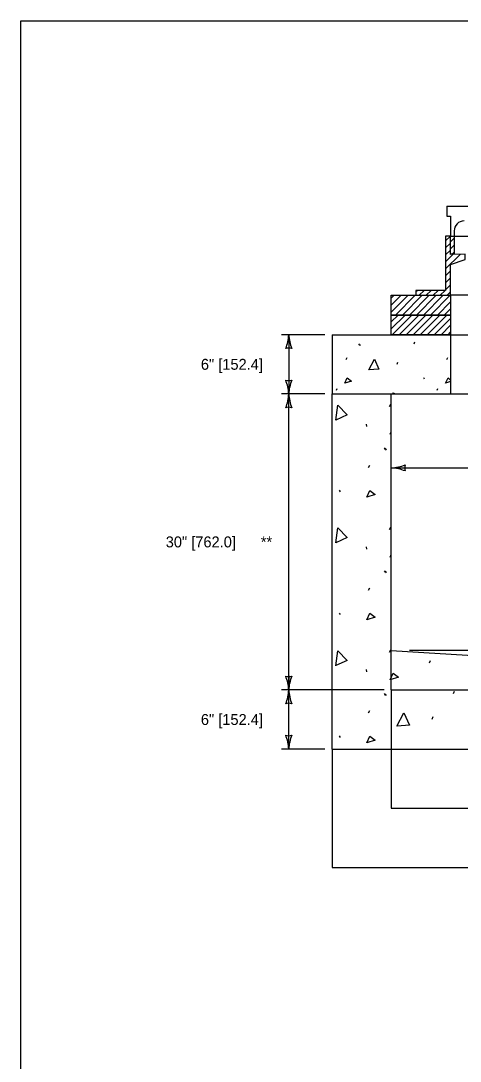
# Model space of a CAD drawing. Extents: x 49991.4 to 50057, y 49987.6 to 50011.4.
# Drawn here: x 49999.38 to 50001.8, y 49993.29 to 49999 of the extents above; entities that cross this region are included whole.
import ezdxf

# ---------------------------------------------------------------- set-up
doc = ezdxf.new("R2010")
doc.units = 0
for name, color, linetype in [('Level 1', 7, 'Continuous'), ('Level 2', 7, 'Continuous'), ('Level 3', 7, 'Continuous'), ('Level 4', 7, 'Continuous')]:
    doc.layers.add(name, color=color, linetype=linetype)

msp = doc.modelspace()

# ---------------------------------------------------------------- linework, layer by layer
at = {"layer": 'Level 1'}
for p, q in [((50001.7226, 49997.9815), (50003.7132, 49997.9815)), ((50001.7226, 49997.9815), (50001.7226, 49997.9273)), ((50001.7226, 49997.9273), (50001.7429, 49997.9273)), ((50001.7429, 49997.9273), (50001.7429, 49997.8173)), ((50001.7632, 49997.846), (50001.7632, 49997.8173)), ((50001.7158, 49997.7903), (50001.7429, 49997.8173)), ((50001.7429, 49997.7853), (50001.7632, 49997.8056)), ((50001.7632, 49997.8173), (50003.6726, 49997.8173)), ((50001.7632, 49997.8173), (50001.7632, 49997.7172)), ((50001.7158, 49997.752), (50001.7429, 49997.7791)), ((50001.7158, 49997.7137), (50001.7429, 49997.7408)), ((50001.7429, 49997.747), (50001.7632, 49997.7673)), ((50001.7515, 49997.7172), (50001.7632, 49997.729)), ((50001.7158, 49997.6371), (50001.7955, 49997.7168)), ((50001.7158, 49997.6754), (50001.7565, 49997.716)), ((50001.7158, 49997.5988), (50001.7429, 49997.6259)), ((50001.7158, 49997.5605), (50001.7429, 49997.5876)), ((50001.5533, 49997.5129), (50001.5599, 49997.5194)), ((50001.5711, 49997.4923), (50001.5982, 49997.5194)), ((50001.6094, 49997.4923), (50001.6365, 49997.5194)), ((50001.6477, 49997.4923), (50001.6748, 49997.5194)), ((50001.686, 49997.4923), (50001.7131, 49997.5194)), ((50001.7158, 49997.5222), (50001.7429, 49997.5493)), ((50001.7243, 49997.4923), (50001.7429, 49997.511)), ((50001.4179, 49997.3994), (50001.5108, 49997.4923)), ((50001.4179, 49997.4377), (50001.4725, 49997.4923)), ((50001.4179, 49997.476), (50001.4342, 49997.4923)), ((50001.4408, 49997.384), (50001.5491, 49997.4923)), ((50001.4791, 49997.384), (50001.5874, 49997.4923)), ((50001.5174, 49997.384), (50001.6257, 49997.4923)), ((50001.5557, 49997.384), (50001.664, 49997.4923)), ((50001.594, 49997.384), (50001.7023, 49997.4923)), ((50001.6323, 49997.384), (50001.7406, 49997.4923)), ((50001.6706, 49997.384), (50001.7429, 49997.4563)), ((50003.6929, 49997.4923), (50001.7429, 49997.4923)), ((50001.7089, 49997.384), (50001.7429, 49997.418)), ((50001.4179, 49997.3088), (50001.4931, 49997.384)), ((50001.4179, 49997.3471), (50001.4548, 49997.384)), ((50001.423, 49997.2757), (50001.5314, 49997.384)), ((50001.4613, 49997.2757), (50001.5697, 49997.384)), ((50001.4996, 49997.2757), (50001.608, 49997.384)), ((50001.5379, 49997.2757), (50001.6463, 49997.384)), ((50001.5762, 49997.2757), (50001.6846, 49997.384)), ((50001.6145, 49997.2757), (50001.7229, 49997.384)), ((50001.6528, 49997.2757), (50001.7429, 49997.3657)), ((50001.6911, 49997.2757), (50001.7429, 49997.3274)), ((50001.0929, 49997.2757), (50001.7429, 49997.2757)), ((50001.0929, 49997.2757), (50001.0929, 49996.9507)), ((50001.7294, 49997.2757), (50001.7429, 49997.2891)), ((50001.7429, 49997.2757), (50001.7429, 49996.9507)), ((50001.7429, 49997.2757), (50003.6929, 49997.2757)), ((50001.2384, 49997.226), (50001.2431, 49997.219)), ((50001.2431, 49997.2233), (50001.2477, 49997.2164)), ((50001.5432, 49997.226), (50001.5478, 49997.2364)), ((50001.1703, 49997.1404), (50001.1749, 49997.1508)), ((50001.4497, 49997.1138), (50001.4543, 49997.1242)), ((50001.7233, 49997.1404), (50001.7279, 49997.1508)), ((50001.594, 49997.04), (50001.5986, 49997.033)), ((50001.7429, 49997.0186), (50001.7152, 49997.0099)), ((50001.0929, 49996.9507), (50001.7429, 49996.9507)), ((50001.0929, 49995.0007), (50001.0929, 49996.9507)), ((50001.0929, 49996.9507), (50004.3429, 49996.9507)), ((50001.1165, 49996.9705), (50001.1211, 49996.9809)), ((50001.4179, 49995.3257), (50001.4179, 49996.9507)), ((50001.6695, 49996.9705), (50001.6741, 49996.9809)), ((50001.4087, 49996.8808), (50001.4145, 49996.8937)), ((50001.2799, 49996.7853), (50001.2814, 49996.7724)), ((50001.4116, 49996.7292), (50001.4179, 49996.7423)), ((50001.4179, 49996.7312), (50001.4116, 49996.7292)), ((50001.3784, 49996.6542), (50001.3842, 49996.6455)), ((50001.3842, 49996.6509), (50001.39, 49996.6422)), ((50001.2933, 49996.5472), (50001.299, 49996.5602)), ((50001.1316, 49996.4217), (50001.1374, 49996.413)), ((50001.4087, 49996.2067), (50001.4145, 49996.2197)), ((50001.2799, 49996.1113), (50001.2814, 49996.0983)), ((50001.4116, 49996.0552), (50001.4179, 49996.0683)), ((50001.4179, 49996.0571), (50001.4116, 49996.0552)), ((50001.3784, 49995.9801), (50001.3842, 49995.9715)), ((50001.3842, 49995.9768), (50001.39, 49995.9682)), ((50001.2933, 49995.8732), (50001.299, 49995.8861)), ((50001.1316, 49995.7476), (50001.1374, 49995.739)), ((50001.4087, 49995.5326), (50001.4145, 49995.5456)), ((50001.4179, 49995.5423), (50004.0179, 49995.3798)), ((50001.6281, 49995.4734), (50001.6338, 49995.4864)), ((50001.2799, 49995.4372), (50001.2814, 49995.4242)), ((50001.3784, 49995.306), (50001.3842, 49995.2974)), ((50001.3842, 49995.3028), (50001.39, 49995.2941)), ((50001.4179, 49995.3257), (50004.0179, 49995.3257)), ((50001.4179, 49995.3257), (50004.0179, 49995.3257)), ((50001.7594, 49995.306), (50001.7652, 49995.319)), ((50001.2933, 49995.1991), (50001.299, 49995.2121)), ((50001.6425, 49995.1659), (50001.6483, 49995.1789)), ((50001.1316, 49995.0735), (50001.1374, 49995.0649)), ((50001.0929, 49995.0007), (50004.3429, 49995.0007)), ((50001.0929, 49995.0007), (50001.0929, 49995.0007))]:
    msp.add_line(p, q, dxfattribs=at)
for points in [[(49999.3835, 49998.9992), (50016.7501, 49998.9992), (50016.7501, 49987.7988), (49999.3835, 49987.7988)], [(50001.7429, 49997.4923), (50001.7429, 49997.6616), (50001.8242, 49997.6887), (50001.8242, 49997.7173), (50001.7429, 49997.7158), (50001.7429, 49997.8173), (50001.7158, 49997.8173), (50001.7158, 49997.5194), (50001.5533, 49997.5194), (50001.5533, 49997.4923)], [(50001.7429, 49997.8173), (50001.7632, 49997.8173), (50001.7632, 49997.7172), (50001.7429, 49997.7172)], [(50001.4179, 49997.4923), (50001.7429, 49997.4923), (50001.7429, 49997.384), (50001.4179, 49997.384)], [(50001.4179, 49997.384), (50001.7429, 49997.384), (50001.7429, 49997.2757), (50001.4179, 49997.2757)]]:
    msp.add_lwpolyline(points, close=True, dxfattribs=at)
for points in [[(50001.2939, 49997.0827), (50001.325, 49997.1415), (50001.3493, 49997.0873), (50001.295, 49997.0827)], [(50001.1622, 49997.0099), (50001.1761, 49997.0388), (50001.1992, 49997.0215), (50001.1622, 49997.0099)], [(50001.7152, 49997.0099), (50001.7291, 49997.0388), (50001.7429, 49997.0284)], [(50001.4265, 49996.9507), (50001.4292, 49996.9563), (50001.4367, 49996.9507)], [(50001.1124, 49996.8067), (50001.1238, 49996.8891), (50001.1755, 49996.8358), (50001.1137, 49996.8071)], [(50001.2832, 49996.3842), (50001.3005, 49996.4202), (50001.3293, 49996.3986), (50001.2832, 49996.3842)], [(50001.1124, 49996.1326), (50001.1238, 49996.2151), (50001.1755, 49996.1617), (50001.1137, 49996.1331)], [(50001.2832, 49995.7101), (50001.3005, 49995.7462), (50001.3293, 49995.7245), (50001.2832, 49995.7101)], [(50001.1124, 49995.4585), (50001.1238, 49995.541), (50001.1755, 49995.4876), (50001.1137, 49995.459)], [(50001.4116, 49995.3811), (50001.4289, 49995.4172), (50001.4578, 49995.3955), (50001.4116, 49995.3811)], [(50001.4477, 49995.1269), (50001.4866, 49995.2005), (50001.517, 49995.1327), (50001.4491, 49995.1269)], [(50001.2832, 49995.036), (50001.3005, 49995.0721), (50001.3293, 49995.0504), (50001.2832, 49995.036)]]:
    msp.add_lwpolyline(points, dxfattribs=at)
msp.add_arc((50001.8174, 49997.846), 0.0542, 89.9504, 180, dxfattribs=at)
at = {"layer": 'Level 3'}
for p, q in [((50001.0529, 49997.2757), (50000.8147, 49997.2757)), ((50000.8547, 49997.2757), (50000.8547, 49996.9507)), ((50001.0529, 49996.9507), (50000.8147, 49996.9507)), ((50000.8547, 49995.3257), (50000.8547, 49996.9507)), ((50001.4179, 49996.5444), (50004.0179, 49996.5444)), ((50001.9384, 49995.5423), (50001.5179, 49995.5423)), ((50000.8547, 49995.4037), (50000.8547, 49995.3257)), ((50001.3779, 49995.3257), (50000.8147, 49995.3257)), ((50000.8547, 49995.0007), (50000.8547, 49995.3257)), ((50001.0529, 49995.0007), (50000.8147, 49995.0007))]:
    msp.add_line(p, q, dxfattribs=at)
for centre, radius, start, end in [((50000.6326, 49997.2848), 0.2223, 337.456, 357.6395), ((50001.0874, 49997.2872), 0.233, 182.8273, 202.0772), ((50000.8547, 49997.1474), 0.0548, 72.1388, 107.8612), ((50000.8547, 49997.0789), 0.0548, 252.1388, 287.8612), ((50000.622, 49996.9392), 0.233, 2.8273, 22.0772), ((50001.0768, 49996.9415), 0.2223, 157.456, 177.6395), ((50000.6326, 49996.9598), 0.2223, 337.456, 357.6395), ((50001.0874, 49996.9622), 0.233, 182.8273, 202.0772), ((50000.8547, 49996.8224), 0.0548, 72.1388, 107.8612), ((50001.4064, 49996.7771), 0.233, 272.8273, 292.0772), ((50001.4087, 49996.3223), 0.2223, 67.456, 87.6395), ((50001.5461, 49996.5444), 0.0548, 162.1388, 197.8612), ((50000.8547, 49995.4539), 0.0548, 252.1388, 287.8612), ((50000.622, 49995.3142), 0.233, 2.8273, 22.0772), ((50001.0768, 49995.3165), 0.2223, 157.456, 177.6395), ((50000.6326, 49995.3348), 0.2223, 337.456, 357.6395), ((50001.0874, 49995.3372), 0.233, 182.8273, 202.0772), ((50000.8547, 49995.1974), 0.0548, 72.1388, 107.8612), ((50000.8547, 49995.1289), 0.0548, 252.1388, 287.8612), ((50000.622, 49994.9892), 0.233, 2.8273, 22.0772), ((50001.0768, 49994.9915), 0.2223, 157.456, 177.6395)]:
    msp.add_arc(centre, radius, start, end, dxfattribs=at)
at = {"layer": 'Level 4'}
for p, q in [((50001.4179, 49995.3257), (50001.4179, 49994.6757)), ((50001.0929, 49995.0007), (50001.0929, 49994.6757)), ((50001.0929, 49994.6757), (50001.0929, 49994.3507)), ((50001.4179, 49994.6757), (50004.0179, 49994.6757)), ((50001.0929, 49994.3507), (50004.3429, 49994.3507))]:
    msp.add_line(p, q, dxfattribs=at)

# ---------------------------------------------------------------- texts
at = {"layer": 'Level 2'}
for s, p in [('6" [152.4]', (50000.3722, 49997.0832)), ('30" [762.0]', (50000.1792, 49996.1082)), ('**', (50000.7014, 49996.108)), ('6" [152.4]', (50000.3722, 49995.1332))]:
    msp.add_text(s, height=0.06, dxfattribs=at).set_placement(p)

doc.saveas('drawing.dxf')
